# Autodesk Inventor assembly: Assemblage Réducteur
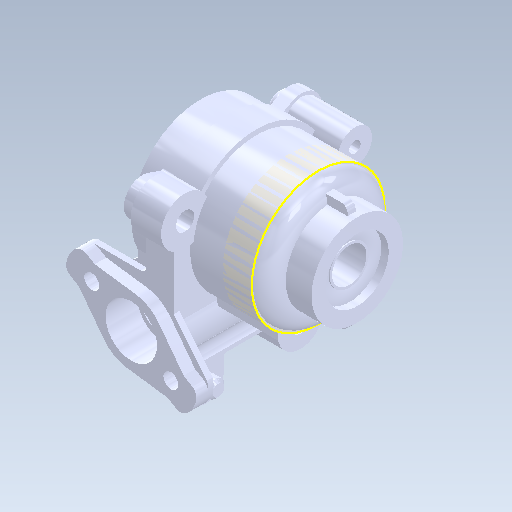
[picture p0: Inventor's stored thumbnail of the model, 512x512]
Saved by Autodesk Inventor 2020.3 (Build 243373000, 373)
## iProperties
Created: 2019-01
Part Number: Assemblage Réducteur
Document SubType Name: Assembly
Designer: ficho
Mass: 11.9098 g
Surface Area: 125.92 cm^2
Volume: 8.20282 cm^3
Density: 1.45192 g/cm^3
Sending System: SolidWorks 2015
Last Author: adrien
Last Saved: 2019-01-14
Author: ficho
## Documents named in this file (7)
- D:\travail\année 2020-2021\2I2D\laveur de vitre\Assemblage Réducteur.iam
- D:\travail\année 2020-2021\2I2D\laveur de vitre\Roulement 13x5x6.ipt
- D:\travail\année 2020-2021\2I2D\laveur de vitre\Lave vitre\4 Dossier Ressources\1 Modèles 3D Solidworks\Rondelle D10.ipt
- D:\travail\année 2020-2021\2I2D\laveur de vitre\Rondelle plastique.ipt
- D:\travail\année 2020-2021\2I2D\laveur de vitre\Couvercle réducteur.ipt
- D:\travail\année 2020-2021\2I2D\laveur de vitre\Vis 3x12.ipt
- D:\travail\année 2020-2021\2I2D\laveur de vitre\Lave vitre\4 Dossier Ressources\1 Modèles 3D Solidworks\adaptation inventor\corps réducteur inventor2.iam
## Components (7 placed, 6 different names)
1. Roulement 13x5x6:1
2. Rondelle D10:1
3. Rondelle plastique:1
4. Couvercle réducteur:1 — Logement:1, Placage:1
5. Vis 3x12:1
6. Vis 3x12:2
7. corps réducteur inventor2:1 [sub-assembly] — Logement:1, Placage:1
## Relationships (2: Insert 1, Mate 1)
- Logement:1 [Insert]: Couvercle réducteur:1 ↔ corps réducteur inventor2:1
- Placage:1 [Mate]: Couvercle réducteur:1 ↔ corps réducteur inventor2:1
